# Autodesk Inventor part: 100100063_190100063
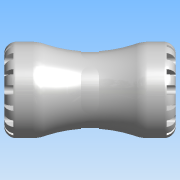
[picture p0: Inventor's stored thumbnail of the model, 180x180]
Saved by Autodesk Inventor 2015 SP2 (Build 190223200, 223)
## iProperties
Created: 2016-12
Part Number: 100100063_190100063
Material: PVC-Piping
Description: PLASSON COUPLER 63X63 SERIES 1
Document SubType Name: Modeling
Designer: KIM
Mass: 95.2094 g
Surface Area: 200.83 cm^2
Volume: 68.0067 cm^3
Density: 1.4 g/cm^3
Appearance: Smooth - White
ILogicFactory: False
Author: KIM
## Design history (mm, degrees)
derived "1001.ipt"
feature "Solid1::1001.ipt"
tag "TaggingFeature1"
body "Solid1"
other parameters: "d4" = 5.25, "d11" = 9.7, "d13" = 9.7, "d14" = 0, "d16" = 360 deg, "d18" = 8 deg, "d19" = 1.26, "d20" = 8 deg, "d21" = 1.26, "d23" = 0, "d25" = 360 deg, "d27" = 41.2, "d28" = 15.75, "d29" = 18.9, "d30" = 18.9, "d31" = 0, "d33" = 0, "d37" = 36.6, "d38" = 1.03, "d43" = 7.875, "d44" = 63, "d45" = 36.6, "d46" = 82.4, "d47" = 103, "d48" = 183, "d50" = 360 deg, "d54" = 0.513, "d_" = 63, "E_" = 103, "H_" = 183, "d12" = 78.75, "d42" = 103, "d52" = 12.125
